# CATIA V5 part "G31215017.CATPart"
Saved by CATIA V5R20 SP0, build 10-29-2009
Part number: G31215017
Revision: 4
Definition: design
Nomenclature: G31215017
Source: made
Description: NOT SPECIFIED
Bounding box of the stored display mesh (mm): x -6 to 17, y -12.31 to 12.31, z -12.5 to 12.5
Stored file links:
  C:\Users\Raffaele\Desktop\3D X SITO CF\BOLEX\23-BUSH REF 312\G31215017.CATPart

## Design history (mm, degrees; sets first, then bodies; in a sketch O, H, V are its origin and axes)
Body1 "MANIFOLD_SOLID_BREP #3605" (main body)
  Solid1: solid without history
Body2 "MANIFOLD_SOLID_BREP #3748"
  Solid2: solid without history
Body3 "MANIFOLD_SOLID_BREP #3891"
  Solid3: solid without history
Body4 "MANIFOLD_SOLID_BREP #4034"
  Solid4: solid without history
Body5 "MANIFOLD_SOLID_BREP #4177"
  Solid5: solid without history
Body6 "MANIFOLD_SOLID_BREP #4322"
  Solid6: solid without history
Body7 "MANIFOLD_SOLID_BREP #4467"
  Solid7: solid without history
Body8 "MANIFOLD_SOLID_BREP #4612"
  Solid8: solid without history
Body9 "MANIFOLD_SOLID_BREP #4757"
  Solid9: solid without history
Body10 "MANIFOLD_SOLID_BREP #4902"
  Solid10: solid without history
Body11 "MANIFOLD_SOLID_BREP #5047"
  Solid11: solid without history
Body12 "MANIFOLD_SOLID_BREP #5192"
  Solid12: solid without history
Body13 "MANIFOLD_SOLID_BREP #5337"
  Solid13: solid without history
Body14 "MANIFOLD_SOLID_BREP #5482"
  Solid14: solid without history
Body15 "MANIFOLD_SOLID_BREP #5627"
  Solid15: solid without history
Body16 "MANIFOLD_SOLID_BREP #5772"
  Solid16: solid without history
Body17 "MANIFOLD_SOLID_BREP #5917"
  Solid17: solid without history
Body18 "MANIFOLD_SOLID_BREP #6062"
  Solid18: solid without history
Body19 "MANIFOLD_SOLID_BREP #6207"
  Solid19: solid without history
Body20 "MANIFOLD_SOLID_BREP #6351"
  Solid20: solid without history
Body21 "MANIFOLD_SOLID_BREP #6494"
  Solid21: solid without history
Body22 "MANIFOLD_SOLID_BREP #6639"
  Solid22: solid without history
Body23 "MANIFOLD_SOLID_BREP #6783"
  Solid23: solid without history
Body24 "MANIFOLD_SOLID_BREP #6926"
  Solid24: solid without history
Body25 "MANIFOLD_SOLID_BREP #7071"
  Solid25: solid without history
